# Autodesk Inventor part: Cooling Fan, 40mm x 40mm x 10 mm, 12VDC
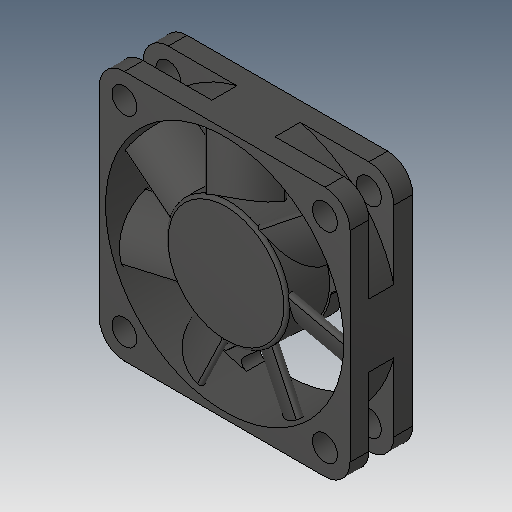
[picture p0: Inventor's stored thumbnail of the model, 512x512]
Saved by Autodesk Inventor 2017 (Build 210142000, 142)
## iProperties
Created: 2005-12
Part Number: Cooling Fan, 40mm x 40mm x 10 mm, 12VDC
Material: Generic
Document SubType Name: Modeling
Designer: DanielSeverino
Density: 1 g/cm^3
Appearance: Default
Author: DanielSeverino
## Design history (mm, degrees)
feature "Solid1"
body "Solid2"
